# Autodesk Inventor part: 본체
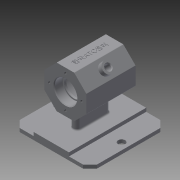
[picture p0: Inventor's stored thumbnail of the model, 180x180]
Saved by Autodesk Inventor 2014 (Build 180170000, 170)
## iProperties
Created: 2018-06
Part Number: 본체
Material: Generic
Document SubType Name: Modeling
Designer: kh
Density: 1 g/cm^3
Appearance: Default
Author: kh
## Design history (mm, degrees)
sketch "Sketch1"
  geometry: L1 (-55, 55)-(55, 55); L2 (55, 55)-(55, -55); L3 (55, -55)-(-55, -55); L4 (-55, -55)-(-55, 55); L5 (-55, 55)-(55, -55); L6 (55, 55)-(-55, -55); 1 further point
  constraints: 12 end point, 2 midpoint, 2 parallel, 1 horizontal, 1 perpendicular
  dimensions: "d0" = 110 distance of L1.start L1.end; "d1" = 110 distance of L1.end L2.end
extrude "Extrusion1" new body sketch "Sketch1" distance "d2" = 5; taper "d3" = 0 deg
sketch "Sketch2"
  geometry: L1 (-55, 25)-(55, 25); L2 (55, 25)-(55, -25); L3 (55, -25)-(-55, -25); L4 (-55, -25)-(-55, 25); L5 (-55, 25)-(55, -25); L6 (55, 25)-(-55, -25); L7 (55, 55)-(-55, 55) reference; 1 further point
  constraints: 12 end point, 2 midpoint, 2 parallel, 1 horizontal, 1 perpendicular
  dimensions: "d4" = 110 distance of L1.start L1.end; "d5" = 30 distance between parallel lines of L1 L7
extrude "Extrusion2" join sketch "Sketch2" distance "d6" = 5; taper "d7" = 0 deg
sketch "Sketch4" dims "d12" = 60
  geometry: L1 (0, 0)-(0, 62); L2 (-12.426, 32)-(-30, 49.574); L3 (-30, 49.574)-(-30, 74.426); L4 (-30, 74.426)-(-12.426, 92); L5 (-12.426, 92)-(12.426, 92); L6 (12.426, 92)-(30, 74.426); L7 (30, 74.426)-(30, 49.574); L8 (30, 49.574)-(12.426, 32); L9 (12.426, 32)-(-12.426, 32); 3 further points
  constraints: 18 end point, 2 coincident, 1 midpoint, 1 point on line, 1 vertical, 1 vertical alignment, 19 other
  dimensions: "d11" = 62 distance of L1.start L1.end
extrude "Extrusion3" join sketch "Sketch4" stored distance "d13" = 70; taper "d14" = 0 deg
sketch "Sketch5"
  geometry: L1 (-19, 5)-(19, 5); L2 (24, 0)-(24, 0); L3 (19, -5)-(-19, -5); L4 (-24, 0)-(-24, 0); L5 (-24, 5)-(24, -5); L6 (24, 5)-(-24, -5); A1 r 5 centre (-19, 0) between (-19, 5) and (-24, 0); A2 r 5 centre (-19, 0) between (-24, 0) and (-19, -5); A3 r 5 centre (19, 0) between (19, -5) and (24, 0); A4 r 5 centre (19, 0) between (24, 0) and (19, 5); 1 further point
  constraints: 12 end point, 8 point on circle, 8 point on line, 8 tangent, 4 centre point, 3 equal radius, 2 midpoint, 2 parallel, 1 horizontal, 1 perpendicular
  dimensions: "d15" = 10 distance of L6.end L5.start; "d16" = 5 radius of A1; "d17" = 38 distance of A3.centre A1.centre
extrude "Extrusion4" join sketch "Sketch5" stored distance "d18" = 70; taper "d19" = 0 deg
sketch "Sketch6"
  geometry: L1 (-35, 74.426)-(35, 74.426) reference; L2 (-35, 49.574)-(-35, 74.426) reference; L3 (-35, 49.574)-(35, 49.574) reference; L4 (35, 74.426)-(35, 49.574) reference; L5 (35, 62)-(-35, 62); L6 (35, 62)-(35, 78); L7 (35, 78)-(23, 78); L8 (23, 78)-(23, 76); L9 (23, 76)-(20, 76); L10 (20, 76)-(20, 87); L11 (20, 87)-(-20, 87); L12 (-20, 87)-(-20, 76); L13 (-20, 76)-(-23, 76); L14 (-23, 76)-(-23, 78); L15 (-23, 78)-(-35, 78); L16 (-35, 78)-(-35, 62); 1 further point
  constraints: 24 end point, 5 perpendicular, 4 parallel, 2 midpoint, 1 collinear, 1 point on line
  dimensions: "d28" = 32 diameter of L7 L5; "d29" = 12 distance of L6.end L7.end; "d30" = 28 diameter of L9 L5; "d31" = 50 diameter of L11 L5; "d32" = 28 diameter of L13 L5; "d33" = 32 diameter of L15 L5; "d34" = 12 distance of L14.end L15.end; "d35" = 3 distance of L12.end L13.end; "d36" = 3 distance of L8.end L9.end
revolve "Revolution1" sketch "Sketch6" stored, may be unused: angle "d37" = 90 deg
chamfer "Chamfer1" distance "d38" = 1; stored, may be unused: second distance "d39" = 2, angle "d40" = 45 deg
workplane "Work Plane2"
  workplane "Work Plane1"
sketch "Sketch7"
  geometry: L1 (-70, -24.853)-(-70, 0) reference; L2 (0, 0)-(0, -24.853) reference; L3 (-70, -12.426)-(0, -12.426); C1 r 8 at (-35, -12.426); 1 further point
  constraints: 3 midpoint, 2 end point, 1 centre point
  dimensions: "d42" = 16 diameter of C1
extrude "Extrusion5" join sketch "Sketch7" stored distance "d43" = 70; taper "d44" = 0 deg
hole "Hole1" diameter "d47" = 8; stored, may be unused: countersink angle "d51" = 90 deg, drill point angle "d53" = 118 deg; dims "d45" = 10, "d46" = 10, "d48" = 6, "d49" = 4, "d50" = 2, "d52" = 30
chamfer "Chamfer2" distance "d54" = 1; stored, may be unused: second distance "d55" = 2, angle "d56" = 45 deg
sketch "Sketch8"
  geometry: L1 (59.887, 8.824)-(10.113, 8.824); L2 (10.113, 8.824)-(10.113, 16.029); L3 (10.113, 16.029)-(59.887, 16.029); L4 (59.887, 16.029)-(59.887, 8.824); L5 (59.887, 8.824)-(10.113, 16.029); L6 (70, 24.853)-(70, 0) reference; L7 (70, 0)-(0, 0) reference; L8 (70, -17.574)-(0, -17.574) reference; 3 further points
  constraints: 2 end point, 1 midpoint, 2 other
  dimensions: "d57" = 35 distance from line of point (35, 12.426) L6; "d59" = 30 distance from line of point (35, 12.426) L8
emboss "Emboss1" sketch "Sketch8" dims "d0" = 110, "d1" = 110, "d11" = 62, "d12" = 60, "d60" = 0.5, "d61" = 0
sketch "Sketch9" dims "d62" = 46
  geometry: L1 (-62, 0)-(-85, 0); C1 r 17 at (-62, 0) reference; 2 further points
  constraints: 2 coincident, 2 end point, 1 horizontal, 1 horizontal alignment, 2 other
hole "Hole2" sketch "Sketch9" at (-85, 0) diameter "d63" = 3.459; stored, may be unused: countersink angle "d67" = 90 deg, drill point angle "d69" = 118 deg; dims "d64" = 8, "d65" = 4, "d66" = 2, "d68" = 10
pattern_circular "Circular Pattern1" dims angle "d71" = 360 deg
mirror "Mirror1"
fillet "Fillet1" dims "d73" = 0.3
fillet "Fillet2" dims "d74" = 3
fillet "Fillet3" dims "d75" = 1
sketch "Sketch10"
  geometry: L1 (-55, -55)-(-55, 55) reference; L2 (-55, 55)-(55, 55) reference; L3 (0, 0)-(28.516, 0); C1 r 5 at (0, 45); C2 r 5 at (0, -45)
  constraints: 2 centre point, 2 end point, 1 parallel, 1 symmetric about line, 1 other
  dimensions: "d76" = 10 diameter of C1; "d77" = 55 distance from line of L1 C1.centre; "d78" = 10 distance from line of C1.centre L2
extrude "Extrusion6" cut sketch "Sketch10" stored distance "d79" = 70; taper "d80" = 0 deg
chamfer "Chamfer3" distance "d81" = 10; stored, may be unused: second distance "d82" = 2, angle "d83" = 45 deg
fillet "Fillet4" dims "d84" = 2
body "Solid1"
node "Projected Loop1"
other parameters: "d41" = 7
